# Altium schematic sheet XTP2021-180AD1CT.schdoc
size 127 x 101 mm
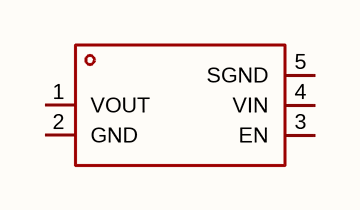
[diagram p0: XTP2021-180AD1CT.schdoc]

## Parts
U?  xtp2021-180ad1ct  [DFN-4_L1.0-W1.0-P0.65-BL-EP]  (value not drawn)

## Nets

Not connected (* = marked no-connect by the designer): U? 1(VOUT) 2(GND) 3(EN) 4(VIN) 5(SGND)

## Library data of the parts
U? = xtp2021-180ad1ct: 输出极性:正极;工作电压:5.5V;输出电压:1.8V;输出电流:300mA;电源纹波抑制比(PSRR):-;输出类型:固定;; Manufacturer: XTX(芯天下); AddInBom: yes; ModelId: bb5c60478e114cecafb4cacfcccae5cc; ModelName: DFN-4_L1.0-W1.0-H0.5-P0.65-BL-EP; ModelTransform: 40.1574,40.1574,0,0,0,0,0.18,0.02,0; Output Configuration: 正极; Voltage - Supply: 5.5V; Output Voltage: 1.8V; Output Current: 300mA; Voltage Dropout: 180mV@(300mA); standby current: 1uA; Output Type: 固定; Number of Outputs: 1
